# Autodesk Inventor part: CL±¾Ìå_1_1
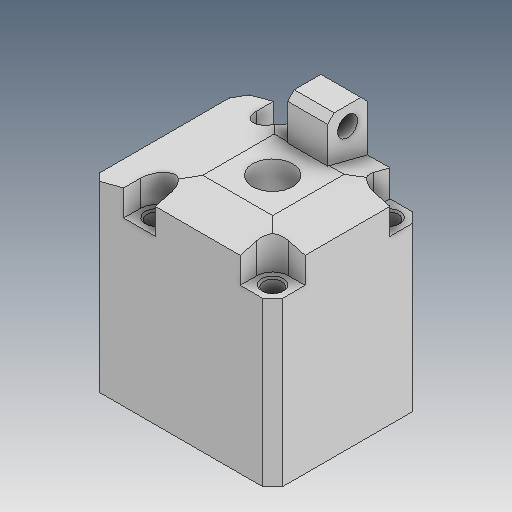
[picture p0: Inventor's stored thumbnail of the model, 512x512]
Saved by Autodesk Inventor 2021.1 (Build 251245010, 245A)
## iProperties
Created: 2019-04
Part Number: CL±¾Ìå_1_1
Material: Ogólny
Document SubType Name: Modeling
Designer: user
Density: 1 g/cm^3
Appearance: Domyślna
Author: user
Revision Number: ÈÎºÎ
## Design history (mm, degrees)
feature "ÊäÈë1"
feature "ÊäÈë2"
feature "ÊäÈë3"
node "Bryła1"
node "Bryła2"
node "Bryła3"
